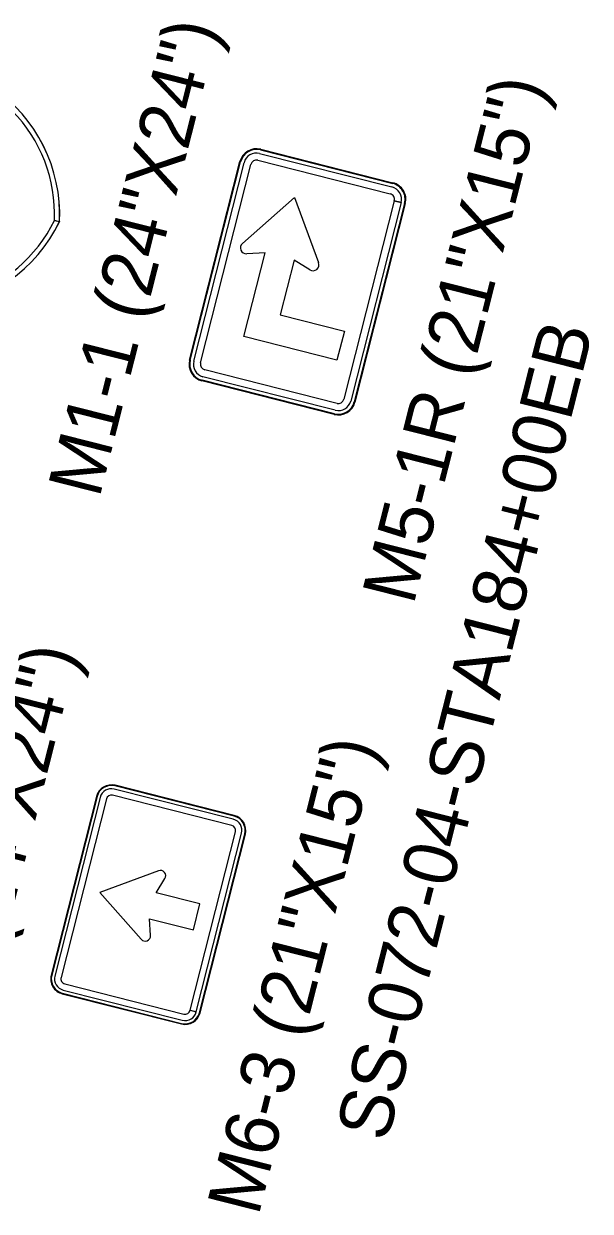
# Model space of a CAD drawing. Extents: x 670257 to 671518, y 737783 to 738188.
# Drawn here: x 670285.04 to 670287.69, y 738151.67 to 738157.23 of the extents above; entities that cross this region are included whole.
import ezdxf

# ---------------------------------------------------------------- set-up
doc = ezdxf.new("R2010")
doc.units = 0
for name, color, linetype in [('Default', 7, 'Continuous'), ('R_SIGN_ANNOT', 7, 'Continuous'), ('R_SIGN_HWY102', 7, 'Continuous')]:
    doc.layers.add(name, color=color, linetype=linetype)

msp = doc.modelspace()

# ---------------------------------------------------------------- linework, layer by layer
at = {"layer": 'Default'}
for p, q in [((670286.149, 738156.6385), (670286.7687, 738156.4813)), ((670286.149, 738156.6385), (670286.149, 738156.6384)), ((670286.1498, 738156.6417), (670286.7695, 738156.4845)), ((670286.1498, 738156.6417), (670286.7695, 738156.4845)), ((670285.8168, 738155.6538), (670286.0527, 738156.5838)), ((670285.8168, 738155.6538), (670286.0527, 738156.5838)), ((670285.8201, 738155.653), (670286.0559, 738156.583)), ((670286.0559, 738156.583), (670286.0559, 738156.583)), ((670286.1367, 738156.59), (670286.7564, 738156.4328)), ((670286.1449, 738156.6223), (670286.7646, 738156.4651)), ((670285.8362, 738155.6489), (670286.072, 738156.5789)), ((670285.8685, 738155.6407), (670286.1043, 738156.5707)), ((670286.7687, 738156.4813), (670286.7687, 738156.4813)), ((670286.7756, 738156.4002), (670286.5398, 738155.4704)), ((670286.8079, 738156.392), (670286.5721, 738155.4623)), ((670286.8241, 738156.3881), (670286.5883, 738155.4582)), ((670286.8273, 738156.3874), (670286.5915, 738155.4574)), ((670286.8273, 738156.3873), (670286.5915, 738155.4574)), ((670286.7756, 738156.4002), (670286.8079, 738156.392)), ((670286.808, 738156.3923), (670286.7757, 738156.4005)), ((670286.8273, 738156.3874), (670286.8241, 738156.3882)), ((670286.8241, 738156.3882), (670286.8241, 738156.3882)), ((670286.8241, 738156.3881), (670286.8273, 738156.3873)), ((670286.3803, 738156.0771), (670286.3068, 738156.1227)), ((670286.3803, 738156.0771), (670286.3068, 738156.1227)), ((670286.3803, 738156.0771), (670286.3068, 738156.1227)), ((670285.8201, 738155.653), (670285.8201, 738155.653)), ((670286.5075, 738155.4512), (670285.8877, 738155.6083)), ((670286.4944, 738155.3995), (670285.8746, 738155.5567)), ((670286.4944, 738155.3995), (670285.8746, 738155.5567)), ((670285.8755, 738155.5599), (670285.8754, 738155.5599)), ((670286.4952, 738155.4027), (670285.8754, 738155.5599)), ((670286.4993, 738155.4189), (670285.8796, 738155.576)), ((670286.5883, 738155.4582), (670286.5883, 738155.4582)), ((670286.4952, 738155.4027), (670286.4952, 738155.4027))]:
    msp.add_line(p, q, dxfattribs=at)
for points in [[(670286.0647, 738156.2009), (670286.3089, 738156.4157), (670286.4212, 738156.1105)], [(670286.0647, 738156.2009), (670286.3089, 738156.4157), (670286.4212, 738156.1105)], [(670286.0647, 738156.2009), (670286.3089, 738156.4157), (670286.4212, 738156.1105)], [(670286.3068, 738156.1227), (670286.2416, 738155.8657), (670286.5417, 738155.7896), (670286.5073, 738155.654), (670286.0716, 738155.7645), (670286.1712, 738156.1571), (670286.0849, 738156.152)], [(670286.3068, 738156.1227), (670286.2416, 738155.8657), (670286.5417, 738155.7896), (670286.5073, 738155.654), (670286.0716, 738155.7645), (670286.1712, 738156.1571), (670286.0849, 738156.152)], [(670286.3068, 738156.1227), (670286.2416, 738155.8657), (670286.5417, 738155.7896), (670286.5073, 738155.654), (670286.0716, 738155.7645), (670286.1712, 738156.1571), (670286.0849, 738156.152)]]:
    msp.add_lwpolyline(points, dxfattribs=at)
for centre, major_axis, start_param, end_param in [((670286.1301, 738156.5642), (-0.0197, -0.0775), 3.141593, 4.712389), ((670286.1301, 738156.5642), (-0.0197, -0.0775), 3.141593, 4.712389), ((670286.1301, 738156.5642), (-0.0188, -0.0743), 3.141593, 4.712389), ((670286.1301, 738156.5642), (-0.0147, -0.0581), 3.141593, 4.712389), ((670286.1301, 738156.5642), (-0.0066, -0.0258), 3.141593, 4.712389), ((670286.7499, 738156.407), (-0.0188, -0.0743), 1.570796, 3.141593), ((670286.7499, 738156.407), (-0.0197, -0.0775), 1.570796, 3.141593), ((670286.7499, 738156.407), (-0.0197, -0.0775), 1.570796, 3.141593), ((670286.7499, 738156.407), (-0.0066, -0.0258), 1.570796, 3.141593), ((670286.7499, 738156.407), (-0.0147, -0.0581), 1.570796, 3.141593), ((670286.0832, 738156.1799), (-0.0069, -0.0271), 4.111136, 6.59038), ((670286.0832, 738156.1799), (-0.0069, -0.0271), 4.111136, 6.59038), ((670286.0832, 738156.1799), (-0.0069, -0.0271), 4.111136, 6.59038), ((670286.395, 738156.1009), (0.0069, 0.0271), 2.834398, 5.313642), ((670286.395, 738156.1009), (0.0069, 0.0271), 2.834398, 5.313642), ((670286.395, 738156.1009), (0.0069, 0.0271), 2.834398, 5.313642), ((670285.8943, 738155.6342), (-0.0197, -0.0775), 4.712389, 6.283185), ((670285.8943, 738155.6342), (-0.0197, -0.0775), 4.712389, 6.283185), ((670285.8943, 738155.6342), (-0.0188, -0.0743), 4.712389, 6.283185), ((670285.8943, 738155.6342), (-0.0147, -0.0581), 4.712389, 6.283185), ((670285.8943, 738155.6342), (-0.0066, -0.0258), 4.712389, 6.283185), ((670286.514, 738155.477), (-0.0066, -0.0258), 0, 1.570796), ((670286.514, 738155.477), (-0.0197, -0.0775), 0, 1.570796), ((670286.514, 738155.477), (-0.0197, -0.0775), 0, 1.570796), ((670286.514, 738155.477), (-0.0188, -0.0743), 0, 1.570796), ((670286.514, 738155.477), (-0.0147, -0.0581), 0, 1.570796)]:
    msp.add_ellipse(centre, major_axis=major_axis, ratio=0.999544, start_param=start_param, end_param=end_param, dxfattribs=at)
at = {"layer": 'R_SIGN_HWY102'}
for p, q in [((670285.4637, 738153.6444), (670285.4636, 738153.6445)), ((670286.0216, 738153.5029), (670285.4637, 738153.6444)), ((670285.4673, 738153.659), (670285.4673, 738153.659)), ((670286.0252, 738153.5175), (670285.4673, 738153.659)), ((670286.026, 738153.5204), (670285.468, 738153.6619)), ((670285.468, 738153.6619), (670285.4681, 738153.6619)), ((670286.026, 738153.5204), (670285.4681, 738153.6619)), ((670285.4681, 738153.6619), (670285.4681, 738153.6619)), ((670285.3806, 738153.6098), (670285.1683, 738152.7727)), ((670285.3806, 738153.6098), (670285.1683, 738152.7727)), ((670285.3835, 738153.6091), (670285.1712, 738152.772)), ((670285.3981, 738153.6054), (670285.1857, 738152.7683)), ((670285.4271, 738153.598), (670285.2148, 738152.7609)), ((670285.3806, 738153.6098), (670285.3806, 738153.6098)), ((670285.3806, 738153.6098), (670285.3806, 738153.6098)), ((670285.3835, 738153.6091), (670285.3835, 738153.6091)), ((670285.3981, 738153.6054), (670285.3981, 738153.6054)), ((670285.4271, 738153.598), (670285.4271, 738153.598)), ((670285.4563, 738153.6154), (670285.4563, 738153.6154)), ((670286.0142, 738153.4739), (670285.4563, 738153.6154)), ((670286.0142, 738153.4739), (670286.0142, 738153.4739)), ((670286.0216, 738153.5029), (670286.0216, 738153.5029)), ((670286.0252, 738153.5175), (670286.0253, 738153.5175)), ((670286.026, 738153.5204), (670286.026, 738153.5204)), ((670286.026, 738153.5204), (670286.026, 738153.5204)), ((670285.8193, 738152.6079), (670286.0315, 738153.4447)), ((670285.8484, 738152.6005), (670286.0606, 738153.4373)), ((670285.8628, 738152.5966), (670286.0751, 738153.4336)), ((670285.8657, 738152.5958), (670286.078, 738153.4329)), ((670285.8657, 738152.5959), (670286.078, 738153.4329)), ((670286.0316, 738153.4447), (670286.0315, 738153.4447)), ((670286.0606, 738153.4373), (670286.0606, 738153.4374)), ((670286.0752, 738153.4337), (670286.0751, 738153.4336)), ((670286.078, 738153.4329), (670286.0781, 738153.4329)), ((670286.078, 738153.4329), (670286.0781, 738153.4329)), ((670285.1683, 738152.7727), (670285.1683, 738152.7727)), ((670285.1683, 738152.7727), (670285.1683, 738152.7727)), ((670285.1712, 738152.772), (670285.1712, 738152.772)), ((670285.1857, 738152.7683), (670285.1857, 738152.7683)), ((670285.2148, 738152.761), (670285.2148, 738152.7609)), ((670285.2211, 738152.6882), (670285.779, 738152.5467)), ((670285.2211, 738152.6882), (670285.2211, 738152.6882)), ((670285.2248, 738152.7027), (670285.2248, 738152.7027)), ((670285.2248, 738152.7027), (670285.7827, 738152.5612)), ((670285.2322, 738152.7318), (670285.7901, 738152.5903)), ((670285.2322, 738152.7318), (670285.2322, 738152.7318)), ((670285.2204, 738152.6853), (670285.2203, 738152.6853)), ((670285.2203, 738152.6853), (670285.7783, 738152.5438)), ((670285.2204, 738152.6853), (670285.2204, 738152.6853)), ((670285.2204, 738152.6853), (670285.7783, 738152.5438)), ((670285.7901, 738152.5903), (670285.7901, 738152.5903)), ((670285.8483, 738152.6003), (670285.8192, 738152.6076)), ((670285.8192, 738152.6076), (670285.8193, 738152.6076)), ((670285.8193, 738152.6079), (670285.8484, 738152.6005)), ((670285.8483, 738152.6003), (670285.8483, 738152.6003)), ((670285.8657, 738152.5958), (670285.8628, 738152.5966)), ((670285.8628, 738152.5966), (670285.8628, 738152.5966)), ((670285.8628, 738152.5966), (670285.8657, 738152.5959)), ((670285.8657, 738152.5959), (670285.8657, 738152.5958)), ((670285.7783, 738152.5438), (670285.7783, 738152.5438)), ((670285.7783, 738152.5438), (670285.7783, 738152.5438)), ((670285.779, 738152.5467), (670285.779, 738152.5467)), ((670285.7827, 738152.5612), (670285.7827, 738152.5612))]:
    msp.add_line(p, q, dxfattribs=at)
for points in [[(670285.184, 738156.3086), (670285.2077, 738156.3026)], [(670285.2077, 738156.3025), (670285.184, 738156.3085)], [(670285.2075, 738156.3026), (670285.2077, 738156.3025)], [(670285.2077, 738156.3026), (670285.2075, 738156.3026)], [(670285.6712, 738153.2615), (670285.3965, 738153.1603), (670285.5898, 738152.9405)], [(670285.6712, 738153.2615), (670285.3965, 738153.1603), (670285.5898, 738152.9405)], [(670285.6712, 738153.2615), (670285.3965, 738153.1603), (670285.5898, 738152.9405)], [(670285.8654, 738153.1064), (670285.6602, 738153.1584), (670285.7013, 738153.2246)], [(670285.8654, 738153.1064), (670285.6602, 738153.1584), (670285.7013, 738153.2246)], [(670285.8654, 738153.1064), (670285.6602, 738153.1584), (670285.7013, 738153.2246)], [(670285.6338, 738152.9586), (670285.6293, 738153.0364), (670285.8344, 738152.9844), (670285.8654, 738153.1064)], [(670285.6338, 738152.9586), (670285.6293, 738153.0364), (670285.8344, 738152.9844), (670285.8654, 738153.1064)], [(670285.6338, 738152.9586), (670285.6293, 738153.0364), (670285.8344, 738152.9844), (670285.8654, 738153.1064)]]:
    msp.add_lwpolyline(points, dxfattribs=at)
for centre, radius, start, end in [((670284.4897, 738156.336), 0.7188, 357.337, 114.1302), ((670284.4897, 738156.336), 0.7188, 357.337, 114.1302), ((670284.4897, 738156.336), 0.7186, 357.3411, 114.1164), ((670284.4897, 738156.336), 0.6949, 357.7406, 91.0045), ((670284.5602, 738156.6147), 0.6949, 240.5936, 333.8585), ((670284.5602, 738156.6147), 0.7188, 217.4679, 334.2621), ((670284.5602, 738156.6147), 0.7188, 217.4679, 334.2621), ((670284.5602, 738156.6147), 0.7186, 217.4817, 334.258)]:
    msp.add_arc(centre, radius, start, end, dxfattribs=at)
for centre, major_axis, start_param, end_param in [((670285.4504, 738153.5921), (0.0177, 0.0698), 0, 1.570796), ((670285.4504, 738153.5921), (0.0177, 0.0698), 0, 1.570796), ((670285.4504, 738153.5921), (0.017, 0.0669), 0, 1.570796), ((670285.4504, 738153.5921), (0.0133, 0.0523), 0, 1.570796), ((670285.4504, 738153.5921), (0.0059, 0.0233), 0, 1.570796), ((670286.0083, 738153.4506), (0.0059, 0.0233), 4.712389, 6.283185), ((670286.0083, 738153.4506), (0.0133, 0.0523), 4.712389, 6.283185), ((670286.0083, 738153.4506), (0.017, 0.0669), 4.712389, 6.283185), ((670286.0083, 738153.4506), (0.0177, 0.0698), 4.712389, 6.283185), ((670286.0083, 738153.4506), (0.0177, 0.0698), 4.712389, 6.283185), ((670285.6799, 738153.2379), (0.0062, 0.0244), 4.405194, 6.884438), ((670285.6799, 738153.2379), (0.0062, 0.0244), 4.405194, 6.884438), ((670285.6799, 738153.2379), (0.0062, 0.0244), 4.405194, 6.884438), ((670285.6087, 738152.9571), (-0.0062, -0.0244), 5.681933, 8.161176), ((670285.6087, 738152.9571), (-0.0062, -0.0244), 5.681933, 8.161176), ((670285.6087, 738152.9571), (-0.0062, -0.0244), 5.681933, 8.161176), ((670285.2381, 738152.7551), (0.0177, 0.0698), 1.570796, 3.141593), ((670285.2381, 738152.7551), (0.0177, 0.0698), 1.570796, 3.141593), ((670285.2381, 738152.7551), (0.017, 0.0669), 1.570796, 3.141593), ((670285.2381, 738152.7551), (0.0133, 0.0523), 1.570796, 3.141593), ((670285.2381, 738152.7551), (0.0059, 0.0233), 1.570796, 3.141593), ((670285.796, 738152.6135), (0.0177, 0.0698), 3.141593, 4.712389), ((670285.796, 738152.6135), (0.0177, 0.0698), 3.141593, 4.712389), ((670285.796, 738152.6135), (0.017, 0.0669), 3.141593, 4.712389), ((670285.796, 738152.6135), (0.0133, 0.0523), 3.141593, 4.712389), ((670285.796, 738152.6135), (0.0059, 0.0233), 3.141593, 4.712389)]:
    msp.add_ellipse(centre, major_axis=major_axis, ratio=0.99981, start_param=start_param, end_param=end_param, dxfattribs=at)

# ---------------------------------------------------------------- texts
at = {"layer": 'Default'}
for s, rotation, p in [('M5-1R (21"X15")', 75.7685, (670286.865, 738154.5019)), ('SS-072-04-STA184+00EB', 75.7685, (670286.7425, 738151.9853)), ('M6-3 (21"X15")', 75.7686, (670286.1391, 738151.6398))]:
    msp.add_text(s, height=0.25, rotation=rotation, dxfattribs=at).set_placement(p)
at = {"layer": 'R_SIGN_ANNOT'}
for p in [(670285.3938, 738155.003), (670284.7336, 738152.0754)]:
    msp.add_text('M1-1 (24"X24")', height=0.25, rotation=75.7686, dxfattribs=at).set_placement(p)

doc.saveas('drawing.dxf')
